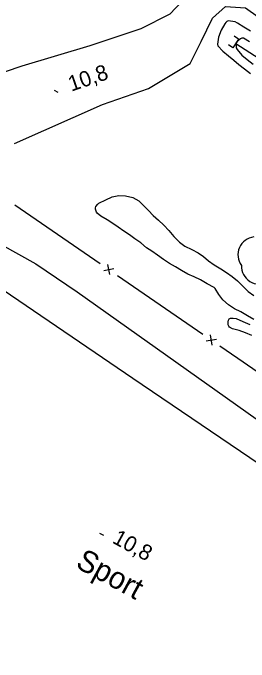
# Model space of a CAD drawing. Extents: x 219136 to 222520, y 5421589 to 5424530.
# Drawn here: x 221435.4 to 221480.9, y 5423389.8 to 5423515.1 of the extents above; entities that cross this region are included whole.
import ezdxf

# ---------------------------------------------------------------- set-up
doc = ezdxf.new("R2010")
doc.units = 0
for name, color, linetype in [('Level 1', 7, 'Continuous'), ('Level 19', 7, 'Continuous'), ('Level 2', 7, 'Continuous'), ('Level 26', 7, 'Continuous'), ('Level 3', 7, 'Continuous'), ('Level 37', 7, 'Continuous'), ('Level 4', 7, 'Continuous'), ('Level 44', 7, 'Continuous'), ('Level 56', 7, 'Continuous')]:
    doc.layers.add(name, color=color, linetype=linetype)

msp = doc.modelspace()

# ---------------------------------------------------------------- linework, layer by layer
at = {"layer": 'Level 1'}
msp.add_lwpolyline([(221481.17, 5423511.62), (221479.86, 5423512.36), (221478.66, 5423513.14), (221478.17, 5423513.43), (221476.86, 5423513.6), (221476.61, 5423513.46), (221476.4, 5423513.27), (221476.21, 5423513.02), (221475.52, 5423511.79), (221475.01, 5423510.44), (221474.77, 5423509.09), (221474.88, 5423508.81), (221475.84, 5423507.72), (221476.93, 5423506.85), (221477.92, 5423505.98), (221478.91, 5423505.17), (221480.01, 5423504.36), (221481.16, 5423503.45)], dxfattribs=at)
at = {"layer": 'Level 19'}
for points in [[(221396.73, 5423573.72), (221408.63, 5423565.86), (221423.2, 5423556.9), (221434.71, 5423548.5), (221448.26, 5423538.11), (221461.01, 5423528.78), (221469.77, 5423522.68), (221469.13, 5423518.71), (221465.61, 5423514.92), (221460, 5423512.09), (221450.19, 5423508.8), (221437.04, 5423504.83), (221427.2, 5423501.53)], [(221435.67, 5423489.92), (221452.64, 5423497.48), (221461.47, 5423500.51), (221469.55, 5423505.36), (221471.66, 5423509.64), (221473.85, 5423514.15), (221476.32, 5423516.36), (221480.18, 5423516.14), (221486.62, 5423511.54), (221500.99, 5423501.74), (221513.95, 5423493.66), (221526.9, 5423485.19), (221540.31, 5423475.77), (221555.17, 5423465.85), (221570.47, 5423455.09), (221587.08, 5423443.28)]]:
    msp.add_lwpolyline(points, dxfattribs=at)
at = {"layer": 'Level 2'}
for points in [[(221480.94, 5423509.58), (221479.78, 5423510.29), (221479.49, 5423510.28), (221479.24, 5423510.15), (221478.62, 5423509.68), (221478.48, 5423509.45), (221478.39, 5423509.21), (221478.4, 5423508.39), (221478.57, 5423508.05)], [(221478.57, 5423508.05), (221479.45, 5423506.99), (221480.53, 5423506.16), (221481.68, 5423505.24)], [(221481.8, 5423455.91), (221480.59, 5423456.66), (221479.27, 5423457.42), (221478.08, 5423457.97), (221476.92, 5423458.75), (221475.8, 5423459.72), (221475.04, 5423460.74), (221474.37, 5423461.92), (221474.14, 5423462.08), (221472.78, 5423462.8), (221471.49, 5423463.57), (221470.26, 5423464.18), (221469.09, 5423464.67), (221467.87, 5423465.38), (221466.67, 5423466.11), (221465.54, 5423466.73), (221464.38, 5423467.54), (221463.23, 5423468.35), (221462.16, 5423469.1), (221461.12, 5423469.79), (221459.98, 5423470.7), (221458.88, 5423471.48), (221457.8, 5423472.27), (221456.74, 5423473.01), (221455.65, 5423473.75), (221454.59, 5423474.48), (221453.52, 5423475.19), (221452.27, 5423475.87), (221451.58, 5423476.43), (221451.44, 5423476.68), (221451.26, 5423477.22), (221451.25, 5423477.5), (221451.36, 5423477.77), (221451.7, 5423478.23), (221451.93, 5423478.36), (221453.25, 5423479.03), (221454.48, 5423479.64), (221455.74, 5423479.9), (221457.04, 5423479.83), (221458.45, 5423479.46), (221459.62, 5423478.86), (221460.55, 5423477.94), (221461.48, 5423476.97)], [(221461.48, 5423476.97), (221462.4, 5423475.99), (221463.42, 5423475.09), (221464.45, 5423474.14), (221465.4, 5423473.1), (221466.38, 5423471.95), (221467.49, 5423470.89), (221468.48, 5423470.08), (221469.82, 5423469.42), (221471.05, 5423468.79), (221472.08, 5423468.06), (221473.06, 5423467.23), (221474.16, 5423466.45), (221475.41, 5423465.71), (221476.53, 5423464.98), (221477.61, 5423464.21), (221478.64, 5423463.42), (221479.69, 5423462.33), (221480.73, 5423461.32), (221481.79, 5423460.58)], [(221481.42, 5423452.83), (221480.2, 5423453.36), (221478.95, 5423453.82), (221477.7, 5423454.14), (221477.11, 5423454.42), (221476.96, 5423454.64), (221476.86, 5423454.91), (221476.82, 5423455.2), (221476.83, 5423455.49), (221476.89, 5423455.77), (221477.04, 5423456.03), (221477.27, 5423456.16), (221477.54, 5423456.2), (221477.83, 5423456.2), (221478.39, 5423456.09), (221479.65, 5423455.55), (221481.01, 5423454.96)]]:
    msp.add_lwpolyline(points, dxfattribs=at)
at = {"layer": 'Level 26'}
for p, q in [((221478.86, 5423510.07), (221477.74, 5423508.39)), ((221478.86, 5423510.07), (221478.03, 5423510.63)), ((221477.74, 5423508.39), (221476.91, 5423508.95))]:
    msp.add_line(p, q, dxfattribs=at)
at = {"layer": 'Level 3'}
for p, q in [((221443.31, 5423500.21), (221444.01, 5423499.82)), ((221452.07, 5423414.63), (221452.78, 5423414.24))]:
    msp.add_line(p, q, dxfattribs=at)
at = {"layer": 'Level 37'}
for p, q in [((221454.01, 5423464.59), (221453.65, 5423466.56)), ((221452.85, 5423465.4), (221454.82, 5423465.76)), ((221473.77, 5423450.97), (221473.41, 5423452.94)), ((221472.6, 5423451.77), (221474.57, 5423452.13))]:
    msp.add_line(p, q, dxfattribs=at)
for points in [[(221435.72, 5423478.07), (221443.95, 5423472.39)], [(221443.95, 5423472.39), (221452.19, 5423466.71)], [(221455.48, 5423464.44), (221463.71, 5423458.76)], [(221463.71, 5423458.76), (221471.94, 5423453.09)], [(221475.23, 5423450.82), (221478.68, 5423448.44), (221483.48, 5423445.16)]]:
    msp.add_lwpolyline(points, dxfattribs=at)
at = {"layer": 'Level 4'}
msp.add_lwpolyline([(221478.31, 5423509.24), (221488.02, 5423502.98), (221499.5, 5423495.61), (221509.34, 5423489.82), (221520.32, 5423482.18), (221534.09, 5423473.12), (221544.85, 5423465.85), (221554.97, 5423457.75), (221566.8, 5423448.85), (221577.09, 5423441.89), (221587.4, 5423434.46), (221593.59, 5423429.5), (221597.77, 5423427.78), (221601.6, 5423424.16), (221608.43, 5423419.5), (221611.75, 5423416.69), (221615.63, 5423416.23), (221620.4, 5423412.6), (221628.56, 5423406.8), (221635.06, 5423402.15), (221641.59, 5423398.38), (221653.68, 5423388.88)], dxfattribs=at)
at = {"layer": 'Level 44'}
for centre, start, end in [((221482.2, 5423468.44), 96.8844, 216.8844), ((221482.89, 5423466.2), 177.3364, 297.3364)]:
    msp.add_arc(centre, 3.46, start, end, dxfattribs=at)
at = {"layer": 'Level 56'}
for points in [[(221433.06, 5423470.41), (221439.75, 5423466.68), (221447.71, 5423461.28), (221486.25, 5423433.92), (221518.89, 5423410.9), (221521.9, 5423407.66), (221524.03, 5423404.3), (221526.87, 5423398.29), (221528.13, 5423391.9), (221528.45, 5423385.47)], [(221433.49, 5423461.67), (221458.44, 5423444.61), (221484.83, 5423426.69), (221513.04, 5423407.4), (221516.26, 5423404.15), (221518.24, 5423400.61), (221520.35, 5423395.27), (221521.21, 5423390.88), (221521.64, 5423385.78)]]:
    msp.add_lwpolyline(points, dxfattribs=at)

# ---------------------------------------------------------------- texts
at = {"layer": 'Level 3'}
for rotation, p in [(18.9799, (221446.61, 5423499.92)), (331.383, (221454.32, 5423412.89))]:
    msp.add_text('10,8', height=3, rotation=rotation, dxfattribs=at).set_placement(p)
at = {"layer": 'Level 56'}
msp.add_text('Sport', height=4.2, rotation=331.383, dxfattribs=at).set_placement((221447.22, 5423408.16))

doc.saveas('drawing.dxf')
